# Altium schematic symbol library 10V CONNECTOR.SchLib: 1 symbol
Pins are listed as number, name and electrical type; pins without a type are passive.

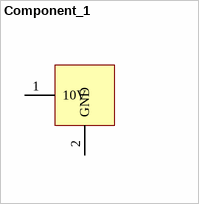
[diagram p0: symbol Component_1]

## Component_1
designator U?, comment Used in BOM report
SymbolVersion: use current date i.e. 2008-05-20; SymbolCreator: Use a-id; CompType: Used in some BOM reports.  Useful for finding later.; U/M: EA, IN, or GM
footprint PCBComponent_1
pins: 1 10V, 2 GND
